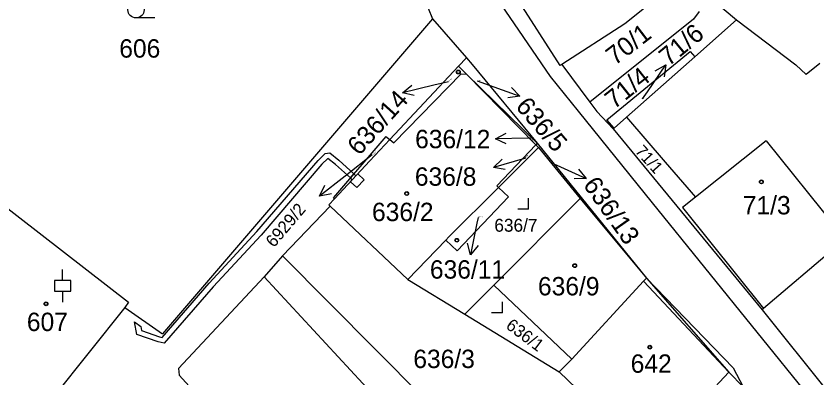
# Model space of a CAD drawing. Extents: x -593183 to -588034, y -1130415 to -1124994.
# Drawn here: x -591094.9 to -591020.9, y -1128820.6 to -1128787.1 of the extents above; entities that cross this region are included whole.
import ezdxf

# ---------------------------------------------------------------- set-up
doc = ezdxf.new("R2010")
doc.units = 0
for name, color, linetype in [('Vrstva 1', 7, 'Continuous'), ('Vrstva 16', 7, 'Continuous'), ('Vrstva 18', 7, 'Continuous'), ('Vrstva 19', 7, 'Continuous'), ('Vrstva 25', 7, 'Continuous'), ('Vrstva 27', 7, 'Continuous'), ('Vrstva 4', 7, 'Continuous')]:
    doc.layers.add(name, color=color, linetype=linetype)

msp = doc.modelspace()

# ---------------------------------------------------------------- linework, layer by layer
at = {"layer": 'Vrstva 1'}
for p, q in [((-591068.59, -1128757.64), (-591056.4, -1128787.36)), ((-591049.86, -1128783.53), (-591044.63, -1128791.68)), ((-591032.83, -1128783.16), (-591038.62, -1128787.83)), ((-591031.12, -1128785.08), (-591028.3, -1128787.45)), ((-591031.75, -1128786.68), (-591032.27, -1128787.38)), ((-591056.4, -1128787.36), (-591081.35, -1128816.5)), ((-591056.4, -1128787.36), (-591053.27, -1128790.98)), ((-591032.27, -1128787.38), (-591041.87, -1128795.06)), ((-591028.3, -1128787.45), (-591032.17, -1128790.88)), ((-591028.3, -1128787.45), (-591022.81, -1128791.63)), ((-591038.62, -1128787.83), (-591044.46, -1128791.57)), ((-591053.27, -1128790.98), (-591053.99, -1128791.75)), ((-591053.27, -1128790.98), (-591052.75, -1128791.6)), ((-591032.17, -1128790.88), (-591038.47, -1128796.46)), ((-591053.99, -1128791.75), (-591060.34, -1128798.53)), ((-591053.99, -1128791.75), (-591053.25, -1128792.47)), ((-591052.75, -1128791.6), (-591046.72, -1128798.85)), ((-591044.46, -1128791.57), (-591044.63, -1128791.68)), ((-591044.46, -1128791.57), (-591041.87, -1128795.06)), ((-591022.81, -1128791.63), (-591021.87, -1128792.5)), ((-591020.62, -1128791.5), (-591021.87, -1128792.5)), ((-591053.75, -1128792.45), (-591059.98, -1128798.82)), ((-591053.75, -1128792.45), (-591053.25, -1128792.47)), ((-591046.87, -1128799.01), (-591053.25, -1128792.47)), ((-591053.25, -1128792.47), (-591046.72, -1128798.85)), ((-591110.82, -1128793.11), (-591084.52, -1128813.58)), ((-591041.87, -1128795.06), (-591041.23, -1128795.93)), ((-591041.23, -1128795.93), (-591039.7, -1128797.55)), ((-591038.47, -1128796.46), (-591039.61, -1128797.47)), ((-591038.47, -1128796.46), (-591034.9, -1128800.62)), ((-591039.61, -1128797.47), (-591039.7, -1128797.55)), ((-591039.7, -1128797.55), (-591025.95, -1128814.27)), ((-591060.71, -1128798.24), (-591065.56, -1128803.89)), ((-591060.34, -1128798.53), (-591062.21, -1128800.51)), ((-591060.71, -1128798.24), (-591060.34, -1128798.53)), ((-591060.34, -1128798.53), (-591059.98, -1128798.82)), ((-591046.87, -1128799.01), (-591050.47, -1128802.81)), ((-591046.62, -1128799.27), (-591050.32, -1128802.95)), ((-591046.72, -1128798.85), (-591046.87, -1128799.01)), ((-591046.62, -1128799.27), (-591046.87, -1128799.01)), ((-591046.72, -1128798.85), (-591036.62, -1128811.35)), ((-591046.62, -1128799.27), (-591042.76, -1128803.99)), ((-591065.47, -1128804.01), (-591062.21, -1128800.51)), ((-591034.9, -1128800.62), (-591032.11, -1128803.87)), ((-591050.32, -1128802.95), (-591054.91, -1128807.52)), ((-591050.47, -1128802.81), (-591050.32, -1128802.95)), ((-591050.32, -1128802.95), (-591049.39, -1128803.83)), ((-591049.39, -1128803.83), (-591054.12, -1128808.83)), ((-591032.11, -1128803.87), (-591033.29, -1128804.81)), ((-591065.98, -1128804.56), (-591065.47, -1128804.01)), ((-591065.98, -1128804.56), (-591065.86, -1128804.68)), ((-591065.47, -1128804.01), (-591065.56, -1128803.89)), ((-591042.76, -1128803.99), (-591050.73, -1128811.99)), ((-591042.76, -1128803.99), (-591036.62, -1128811.35)), ((-591065.86, -1128804.68), (-591070.26, -1128809.27)), ((-591065.86, -1128804.68), (-591058.68, -1128811.48)), ((-591033.29, -1128804.81), (-591025.8, -1128814.14)), ((-591054.91, -1128807.52), (-591055.19, -1128807.82)), ((-591055.19, -1128807.82), (-591058.68, -1128811.48)), ((-591054.12, -1128808.83), (-591055.19, -1128807.82)), ((-591018.28, -1128807.73), (-591025.8, -1128814.14)), ((-591070.26, -1128809.27), (-591071.96, -1128811.21)), ((-591070.26, -1128809.27), (-591055.5, -1128824.15)), ((-591071.96, -1128811.21), (-591079.88, -1128819.69)), ((-591058.68, -1128811.48), (-591053.42, -1128814.69)), ((-591050.73, -1128811.99), (-591053.42, -1128814.69)), ((-591050.73, -1128811.99), (-591043.54, -1128818.84)), ((-591036.91, -1128811.63), (-591043.54, -1128818.84)), ((-591036.62, -1128811.35), (-591036.91, -1128811.63)), ((-591036.62, -1128811.35), (-591029.03, -1128820.03)), ((-591084.83, -1128814.07), (-591094.84, -1128826.52)), ((-591084.52, -1128813.58), (-591084.83, -1128814.07)), ((-591084.83, -1128814.07), (-591081.35, -1128816.5)), ((-591025.8, -1128814.14), (-591025.95, -1128814.27)), ((-591053.42, -1128814.69), (-591044.71, -1128820)), ((-591043.54, -1128818.84), (-591044.71, -1128820)), ((-591079.88, -1128819.69), (-591079.83, -1128820.33)), ((-591044.71, -1128820), (-591042.14, -1128822.46)), ((-591029.03, -1128820.03), (-591033.18, -1128824.48)), ((-591029.03, -1128820.03), (-591027.7, -1128821.39)), ((-591079.83, -1128820.33), (-591065.57, -1128835.78))]:
    msp.add_line(p, q, dxfattribs=at)
msp.add_lwpolyline([(-591039.61, -1128797.47), (-591040.28, -1128796.7), (-591032.58, -1128790.39), (-591032.17, -1128790.88)], dxfattribs=at)
at = {"layer": 'Vrstva 16'}
for p, q in [((-591054.94, -1128793.19), (-591056.27, -1128793.51)), ((-591052.27, -1128793.11), (-591051.16, -1128793.51)), ((-591037.01, -1128794.77), (-591036.55, -1128794.1)), ((-591047.35, -1128798.4), (-591047.6, -1128798.4)), ((-591061.97, -1128799.93), (-591064.49, -1128801.91)), ((-591047.81, -1128800.25), (-591047.9, -1128800.28)), ((-591045.35, -1128800.7), (-591044.93, -1128800.89)), ((-591052.2, -1128805.73), (-591052.3, -1128806.26))]:
    msp.add_line(p, q, dxfattribs=at)
at = {"layer": 'Vrstva 25'}
for p, q in [((-591082.06, -1128787.28), (-591083.81, -1128787.28)), ((-591036.55, -1128794.1), (-591034.852, -1128791.627)), ((-591056.27, -1128793.51), (-591059.189, -1128794.202)), ((-591051.16, -1128793.51), (-591048.337, -1128794.526)), ((-591047.6, -1128798.4), (-591050.599, -1128798.455)), ((-591047.9, -1128800.28), (-591050.784, -1128801.104)), ((-591044.93, -1128800.89), (-591042.194, -1128802.121)), ((-591064.49, -1128801.91), (-591066.848, -1128803.765)), ((-591047.52, -1128804.95), (-591047.52, -1128803.95)), ((-591047.52, -1128804.95), (-591048.52, -1128804.95)), ((-591052.3, -1128806.26), (-591052.885, -1128809.202)), ((-591090.6, -1128811.56), (-591090.6, -1128810.56)), ((-591090.6, -1128812.56), (-591090.6, -1128813.56)), ((-591049.94, -1128814.55), (-591049.94, -1128813.55)), ((-591049.94, -1128814.55), (-591050.94, -1128814.55))]:
    msp.add_line(p, q, dxfattribs=at)
for points in [[(-591035.83, -1128792.168), (-591034.852, -1128791.627), (-591035.006, -1128792.734)], [(-591058.101, -1128794.458), (-591059.189, -1128794.202), (-591058.331, -1128793.485)], [(-591049.109, -1128793.717), (-591048.337, -1128794.526), (-591049.448, -1128794.658)], [(-591049.59, -1128798.937), (-591050.599, -1128798.455), (-591049.609, -1128797.937)], [(-591049.686, -1128801.31), (-591050.784, -1128801.104), (-591049.96, -1128800.349)], [(-591042.901, -1128801.255), (-591042.194, -1128802.121), (-591043.312, -1128802.167)], [(-591065.753, -1128803.54), (-591066.848, -1128803.765), (-591066.371, -1128802.754)], [(-591052.2, -1128808.319), (-591052.885, -1128809.202), (-591053.18, -1128808.124)]]:
    msp.add_lwpolyline(points, dxfattribs=at)
msp.add_lwpolyline([(-591091.35, -1128812.56), (-591089.85, -1128812.56), (-591089.85, -1128811.56), (-591091.35, -1128811.56)], close=True, dxfattribs=at)
for centre, radius in [((-591083.81, -1128786.53), 0.75), ((-591054.02, -1128792.28), 0.175), ((-591054.02, -1128792.28), 0.15), ((-591026.01, -1128802.44), 0.175), ((-591026.01, -1128802.44), 0.15), ((-591058.79, -1128803.52), 0.175), ((-591058.79, -1128803.52), 0.15), ((-591054.16, -1128807.84), 0.175), ((-591054.16, -1128807.84), 0.15), ((-591043.26, -1128810.19), 0.175), ((-591043.26, -1128810.19), 0.15), ((-591092.13, -1128813.72), 0.175), ((-591092.13, -1128813.72), 0.15), ((-591036.32, -1128817.73), 0.175), ((-591036.32, -1128817.73), 0.15)]:
    msp.add_circle(centre, radius, dxfattribs=at)
at = {"layer": 'Vrstva 27'}
for p, q in [((-591066.99, -1128800.45), (-591066.32, -1128799.82)), ((-591066.32, -1128799.82), (-591065.91, -1128799.77)), ((-591065.91, -1128799.77), (-591065.06, -1128800.44)), ((-591072.63, -1128807.02), (-591066.99, -1128800.45)), ((-591066.63, -1128800.79), (-591072.25, -1128807.36)), ((-591066.07, -1128800.27), (-591066.63, -1128800.79)), ((-591065.38, -1128800.82), (-591066.07, -1128800.27)), ((-591064, -1128802.07), (-591065.38, -1128800.82)), ((-591065.06, -1128800.44), (-591063.68, -1128801.7)), ((-591064, -1128802.07), (-591063.68, -1128801.7)), ((-591063.68, -1128801.7), (-591064, -1128802.07)), ((-591063.82, -1128802.24), (-591064, -1128802.07)), ((-591063.99, -1128802.43), (-591063.82, -1128802.24)), ((-591063.82, -1128802.24), (-591063.48, -1128801.88)), ((-591063.48, -1128801.88), (-591063.82, -1128802.24)), ((-591063.68, -1128801.7), (-591063.48, -1128801.88)), ((-591063.48, -1128801.88), (-591063.31, -1128801.69)), ((-591062.73, -1128802.24), (-591063.41, -1128802.97)), ((-591063.31, -1128801.69), (-591062.73, -1128802.24)), ((-591063.41, -1128802.97), (-591063.99, -1128802.43)), ((-591077.06, -1128811.8), (-591072.63, -1128807.02)), ((-591072.25, -1128807.36), (-591076.68, -1128812.14)), ((-591081.4, -1128816.82), (-591077.06, -1128811.8)), ((-591076.68, -1128812.14), (-591081.22, -1128817.36)), ((-591083.75, -1128816.56), (-591083.94, -1128815.39)), ((-591083.94, -1128815.39), (-591083.36, -1128815.81)), ((-591083.36, -1128815.81), (-591083.31, -1128816.18)), ((-591083.31, -1128816.18), (-591081.63, -1128816.77)), ((-591081.77, -1128817.25), (-591083.75, -1128816.56)), ((-591081.63, -1128816.77), (-591081.4, -1128816.82)), ((-591081.22, -1128817.36), (-591081.77, -1128817.25))]:
    msp.add_line(p, q, dxfattribs=at)
at = {"layer": 'Vrstva 4'}
for p, q in [((-591051.47, -1128784), (-591045.52, -1128792.71)), ((-591045.52, -1128792.71), (-591042.93, -1128795.91)), ((-591042.93, -1128795.91), (-591036.09, -1128804.38)), ((-591025.58, -1128798.63), (-591032.11, -1128803.87)), ((-591025.58, -1128798.63), (-591018.28, -1128807.73)), ((-591036.09, -1128804.38), (-591021.34, -1128822.62)), ((-591071.96, -1128811.21), (-591057.39, -1128827)), ((-591036.91, -1128811.63), (-591029.03, -1128820.03)), ((-591036.62, -1128811.35), (-591028.61, -1128819.63)), ((-591025.95, -1128814.27), (-591019.87, -1128821.86)), ((-591028.61, -1128819.63), (-591027.7, -1128821.39))]:
    msp.add_line(p, q, dxfattribs=at)

# ---------------------------------------------------------------- texts
at = {"layer": 'Vrstva 16'}
for s, height, rotation, p in [('71/6', 1.7, 39.55752, (-591034.583, -1128791.804)), ('636/14', 1.7, 47.95929, (-591063.181, -1128800.089)), ('636/5', 1.7, 310.77891, (-591048.807, -1128795.51)), ('636/13', 1.7, 305.19423, (-591042.549, -1128802.72)), ('6929/2', 1.14, 49.63545, (-591071.064, -1128808.578))]:
    msp.add_text(s, height=height, rotation=rotation, dxfattribs=at).set_placement(p)
for s, p in [('636/12', (-591058.014, -1128799.33)), ('636/8', (-591058.038, -1128802.8)), ('636/11', (-591056.65, -1128811.39))]:
    msp.add_text(s, height=1.7, dxfattribs=at).set_placement(p)
at = {"layer": 'Vrstva 18'}
for s, height, rotation, p in [('70/1', 1.7, 37.36161, (-591039.55, -1128791.72)), ('71/4', 1.7, 38.43153, (-591039.618, -1128795.772)), ('71/1', 1.1, 311.95449, (-591037.75, -1128799.65)), ('6929/2', 0.1, 54.78237, (-591061.82, -1128799.95)), ('636/8', 0.1, 42.73722, (-591047.81, -1128800.25)), ('636/13', 0.1, 306.14553, (-591045.67, -1128800.34))]:
    msp.add_text(s, height=height, rotation=rotation, dxfattribs=at).set_placement(p)
for s, height, p in [('606', 1.7, (-591085.36, -1128790.95)), ('636/5', 0.1, (-591052.27, -1128793.11)), ('71/6', 0.1, (-591037.132, -1128794.77)), ('636/3', 1.7, (-591058.18, -1128819.66))]:
    msp.add_text(s, height=height, dxfattribs=at).set_placement(p)
at = {"layer": 'Vrstva 19'}
for s, height, rotation, p in [('636/14', 0.1, 39.05757, (-591054.94, -1128793.19)), ('636/12', 0.1, 310.31406, (-591047.35, -1128798.4)), ('636/1', 1.14, 323.02728, (-591049.71, -1128815.91))]:
    msp.add_text(s, height=height, rotation=rotation, dxfattribs=at).set_placement(p)
for s, height, p in [('71/3', 1.7, (-591027.73, -1128805.45)), ('636/2', 1.7, (-591062, -1128806.07)), ('636/11', 0.1, (-591052.2, -1128805.73)), ('636/7', 1.19, (-591050.69, -1128807.05)), ('636/9', 1.7, (-591046.66, -1128812.94)), ('607', 1.7, (-591093.9, -1128816.24)), ('642', 1.7, (-591038.09, -1128820.1))]:
    msp.add_text(s, height=height, dxfattribs=at).set_placement(p)

doc.saveas('drawing.dxf')
